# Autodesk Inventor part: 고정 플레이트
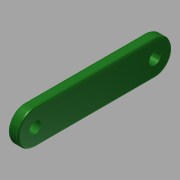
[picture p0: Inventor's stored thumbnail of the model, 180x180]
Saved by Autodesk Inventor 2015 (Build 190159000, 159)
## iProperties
Created: 2017-04
Part Number: 고정 플레이트
Material: 스테인리스강
Document SubType Name: Modeling
Designer: mduedu
Density: 8.08 g/cm^3
Appearance: 매끄러움 - 짙은 산림 녹색
Mass: 9.86033 g
Surface Area: 11.4535 cm^2
Volume: 1.22034 cm^3
Author: mduedu
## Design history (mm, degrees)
sketch "스케치1"
  geometry: L1 (0, 17.5)-(0, -17.5); L2 (-5, 17.5)-(-5, -17.5); L3 (5, -17.5)-(5, 17.5); A1 r 5 centre (0, 17.5) between (5, 17.5) and (-5, 17.5); A2 r 5 centre (0, -17.5) between (-5, -17.5) and (5, -17.5); 2 further points
  constraints: 6 end point, 4 point on circle, 4 tangent, 3 coincident, 2 centre point, 1 midpoint, 1 parallel, 1 vertical
  dimensions: "d0" = 35 distance of L1.start L1.end; "d1" = 5 radius of A2
extrude "돌출1" new body sketch "스케치1" distance "d2" = 3; taper "d3" = 0 deg
fillet "모깎기1" dims "d4" = 0.5
sketch "스케치2"
  geometry: A1 r 5 centre (-17.5, 0) between (-17.5, 5) and (-17.5, -5) reference; A2 r 5 centre (17.5, 0) between (17.5, -5) and (17.5, 5) reference; 3 further points
  constraints: 2 coincident
sketch "스케치3"
  geometry: 3 further points
  constraints: 3 other
hole "구멍1" sketch "스케치3" at (-17.5, 0), (17.5, 0) diameter "d5" = 3.4; stored, may be unused: countersink angle "d9" = 90 deg, drill point angle "d11" = 0 deg; dims "d6" = 6, "d7" = 4, "d8" = 2, "d10" = 8
node "솔리드1"
